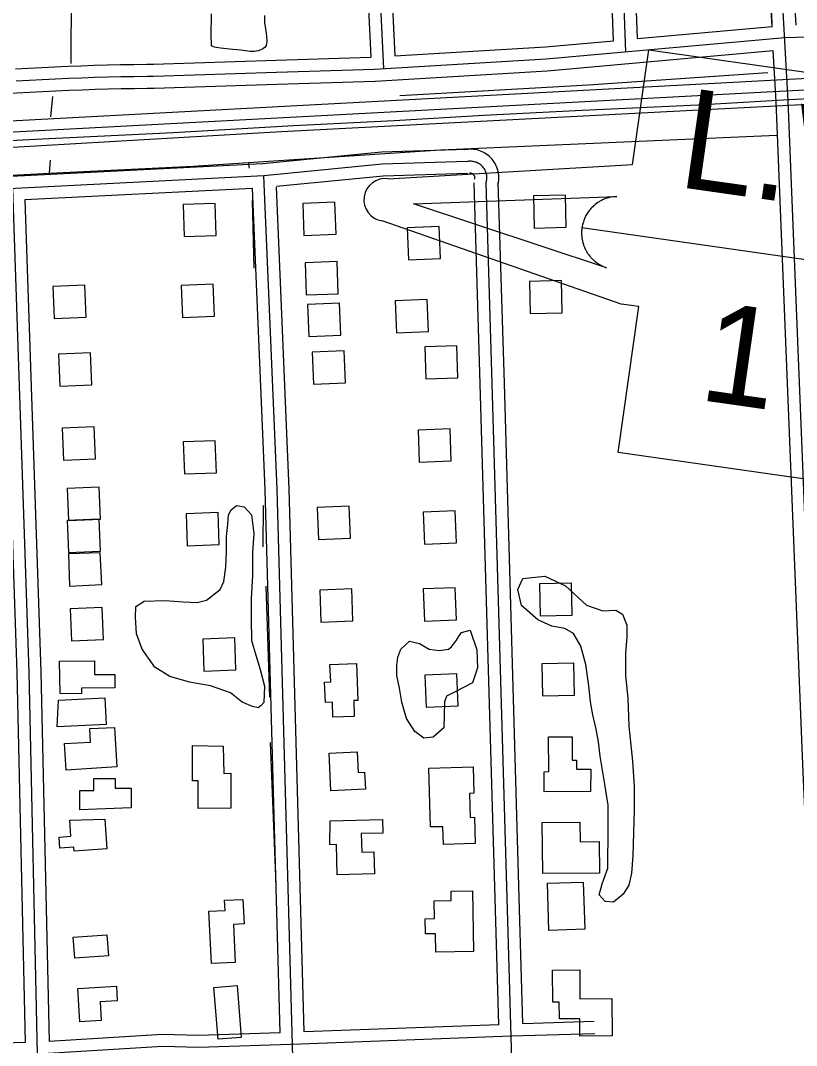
# Model space of a CAD drawing. Extents: x 3508733 to 3546731, y 546897 to 572481.
# Drawn here: x 3525636 to 3526605, y 567338 to 568617 of the extents above; entities that cross this region are included whole.
import ezdxf

# ---------------------------------------------------------------- set-up
doc = ezdxf.new("R2010")
doc.units = 0
for name, color, linetype in [('V-BLDG-OTLN', 7, 'Continuous'), ('V-RAIL-TRAK', 7, 'Continuous'), ('V-ROAD-CNTR', 7, 'Continuous'), ('V-SITE-VEGE', 7, 'Continuous'), ('V-TOPO-SHOR', 7, 'Continuous'), ('V-TOPO-WATR-IDEN', 7, 'Continuous')]:
    doc.layers.add(name, color=color, linetype=linetype)

msp = doc.modelspace()

# ---------------------------------------------------------------- linework, layer by layer
at = {"layer": 'V-BLDG-OTLN'}
for points in [[(3526276.5, 568398.4), (3526277.4, 568358.4), (3526317.4, 568359.3), (3526316.5, 568399.3)], [(3525839.3, 568387.7), (3525840.8, 568347.8), (3525880.7, 568349.2), (3525879.3, 568389.2)], [(3525988.6, 568389), (3525990.1, 568349), (3526030.1, 568350.6), (3526028.6, 568390.5)], [(3526118.8, 568358.7), (3526120.4, 568318.7), (3526160.3, 568320.2), (3526158.8, 568360.2)], [(3525991.4, 568314.9), (3525993, 568274.9), (3526032.9, 568276.4), (3526031.4, 568316.4)], [(3526271.4, 568291.8), (3526272.2, 568251.8), (3526312.2, 568252.7), (3526311.4, 568292.7)], [(3525678.2, 568245.5), (3525718.2, 568247.2), (3525716.5, 568287.2), (3525676.6, 568285.5)], [(3525836.9, 568286.8), (3525838.4, 568246.8), (3525878.3, 568248.2), (3525876.9, 568288.2)], [(3525994.5, 568263.1), (3525996.1, 568223.1), (3526036, 568224.6), (3526034.5, 568264.6)], [(3526104, 568267.5), (3526105.5, 568227.5), (3526145.5, 568229.1), (3526144, 568269)], [(3525685.5, 568160.9), (3525725.5, 568162.6), (3525723.8, 568202.5), (3525683.8, 568200.8)], [(3526000.3, 568203.6), (3526001.8, 568163.6), (3526041.8, 568165.2), (3526040.3, 568205.1)], [(3526140.7, 568210), (3526142.3, 568170), (3526182.2, 568171.5), (3526180.7, 568211.5)], [(3525689.9, 568068.6), (3525729.8, 568070.3), (3525728.2, 568110.3), (3525688.2, 568108.6)], [(3526132.4, 568106.2), (3526133.9, 568066.2), (3526173.9, 568067.7), (3526172.3, 568107.7)], [(3525839.5, 568091.4), (3525840.9, 568051.4), (3525880.9, 568052.9), (3525879.4, 568092.8)], [(3525696.1, 567993.4), (3525736.1, 567995.1), (3525734.4, 568035), (3525694.5, 568033.4)], [(3526006.6, 568009.6), (3526008.2, 567969.6), (3526048.1, 567971.1), (3526046.6, 568011.1)], [(3525696.4, 567953.4), (3525736.4, 567955.1), (3525734.7, 567995), (3525694.7, 567993.4)], [(3525843, 568001.8), (3525844.4, 567961.8), (3525884.4, 567963.3), (3525883, 568003.2)], [(3526138.7, 568003.8), (3526140.3, 567963.8), (3526180.2, 567965.4), (3526178.7, 568005.3)], [(3525697.7, 567911.5), (3525737.7, 567913.2), (3525736, 567953.1), (3525696.1, 567951.5)], [(3526009.7, 567906.4), (3526011.2, 567866.4), (3526051.1, 567867.9), (3526049.6, 567907.9)], [(3526138.9, 567907.8), (3526140.4, 567867.8), (3526180.4, 567869.3), (3526178.8, 567909.3)], [(3526284, 567914.4), (3526284.9, 567874.4), (3526324.9, 567875.3), (3526324, 567915.2)], [(3525699.9, 567842.9), (3525739.9, 567844.6), (3525738.2, 567884.6), (3525698.2, 567882.9)], [(3525863.7, 567845.3), (3525865.1, 567805.3), (3525905.1, 567806.8), (3525903.7, 567846.7)], [(3525685.7, 567777.2), (3525685.2, 567817.5), (3525728.6, 567818), (3525728.8, 567801), (3525754.1, 567801.2), (3525754.3, 567784.5), (3525712.7, 567784), (3525712.7, 567776.9)], [(3526286.9, 567814.3), (3526287.8, 567774.3), (3526327.8, 567775.2), (3526326.9, 567815.2)], [(3526055.5, 567814.8), (3526057.2, 567768.8), (3526052.1, 567768.6), (3526052.9, 567748.7), (3526026.2, 567747.7), (3526025.5, 567766.4), (3526016.9, 567766.1), (3526015.9, 567791.6), (3526023.4, 567791.9), (3526022.5, 567813.6)], [(3526141, 567800.4), (3526142.6, 567760.4), (3526182.5, 567762), (3526181, 567801.9)], [(3525683.7, 567769), (3525741.7, 567771.9), (3525743.4, 567738.7), (3525682.2, 567735.6)], [(3525753.5, 567734.7), (3525756.5, 567685.6), (3525693.4, 567681.8), (3525691.4, 567714.8), (3525723.9, 567716.7), (3525722.9, 567733.6)], [(3526347.7, 567654.9), (3526289.8, 567654.5), (3526289.6, 567679.7), (3526295.5, 567679.8), (3526295.2, 567723.2), (3526324.7, 567723.4), (3526324.9, 567694.1), (3526330.2, 567694.1), (3526330.3, 567682.7), (3526348.1, 567682.8)], [(3525889.4, 567711.5), (3525889.9, 567677.5), (3525898.8, 567677.8), (3525899, 567634.1), (3525858.2, 567633.8), (3525858, 567668.2), (3525850.9, 567668.3), (3525850.9, 567712.3)], [(3526021.7, 567702.8), (3526056.3, 567704.6), (3526057.6, 567678.8), (3526065.7, 567679.2), (3526066.8, 567658), (3526023.4, 567655.8)], [(3526147.9, 567611), (3526145.7, 567684.1), (3526201, 567685.8), (3526202, 567652.9), (3526196.5, 567652.7), (3526197.4, 567622.7), (3526202.8, 567622.9), (3526203.8, 567590), (3526164.2, 567588.8), (3526163.5, 567610.9)], [(3525710.3, 567632.3), (3525710.4, 567656.2), (3525728, 567656.1), (3525728.1, 567671.2), (3525754.5, 567671.1), (3525754.5, 567659.2), (3525774.6, 567659.1), (3525774.5, 567634.5)], [(3525741.7, 567620.5), (3525744, 567583.3), (3525703.3, 567580.7), (3525703, 567585.5), (3525685.4, 567584.3), (3525684.5, 567598.2), (3525699.4, 567599.1), (3525698.1, 567619.2)], [(3526022.6, 567618.4), (3526088.1, 567620.1), (3526088.5, 567603.1), (3526061.6, 567602.4), (3526062.1, 567579.3), (3526077.2, 567579.6), (3526077.9, 567552.1), (3526031.7, 567550.9), (3526030.8, 567588.8), (3526022.5, 567588.6)], [(3526288.1, 567552.5), (3526287.1, 567616.1), (3526334.3, 567616.9), (3526334.7, 567592), (3526358.2, 567592.4), (3526358.8, 567553)], [(3526293.9, 567540.6), (3526338.6, 567541.9), (3526340.4, 567483), (3526295.7, 567481.6)], [(3526200.4, 567531), (3526201.7, 567455.2), (3526154.4, 567454.4), (3526154, 567477.5), (3526141.8, 567477.3), (3526141.5, 567496.2), (3526153, 567496.4), (3526152.6, 567518.7), (3526173.9, 567519.1), (3526173.7, 567530.6)], [(3525874.5, 567440.1), (3525871.5, 567505.7), (3525891.6, 567506.6), (3525891, 567519.2), (3525913.9, 567520.2), (3525915.3, 567489.7), (3525902.1, 567489.1), (3525904.2, 567441.4)], [(3525702.2, 567473.1), (3525744.2, 567476), (3525746, 567449.8), (3525704, 567446.9)], [(3526374.7, 567350), (3526334.4, 567349.7), (3526334.2, 567371.4), (3526308.8, 567371.2), (3526308.6, 567392.1), (3526300.7, 567392), (3526300.3, 567432), (3526334.1, 567432.2), (3526334.4, 567396.2), (3526374.3, 567396.5)], [(3525710.6, 567367.5), (3525707.9, 567409), (3525756, 567412.1), (3525757.1, 567393.7), (3525735.6, 567392.4), (3525737.1, 567369.2)], [(3525883, 567345.8), (3525877.7, 567410.4), (3525906.6, 567412.7), (3525911.8, 567348.1)]]:
    msp.add_lwpolyline(points, close=True, dxfattribs=at)
at = {"layer": 'V-RAIL-TRAK'}
msp.add_lwpolyline([(3524938.2, 568432.3), (3525056, 568438.4), (3525184.8, 568444.9), (3525309.6, 568450), (3525443.1, 568457.1), (3525498.6, 568460.8), (3525527.5, 568462.7), (3525663.6, 568469.7), (3525827.4, 568477.6), (3525977, 568486.2), (3526102.7, 568492.6), (3526214.5, 568499.4), (3526337.1, 568505.5), (3526481.3, 568512.2), (3526595.6, 568518.7), (3526628.2, 568520.6), (3526822.2, 568530.2), (3527016.6, 568540.8), (3527139.8, 568547.4), (3527180.4, 568549.6), (3527314.3, 568557.8), (3527408.8, 568562.5)], dxfattribs=at)
at = {"layer": 'V-ROAD-CNTR'}
for points in [[(3526004.6, 570572), (3526009.4, 570400.2), (3526023.7, 569984.7), (3526032.2, 569739.6), (3526043.8, 569339.4), (3526061.5, 568823.8), (3526073.6, 568571.6)], [(3526019.6, 570572.4), (3526024.4, 570400.7), (3526038.7, 569985.2), (3526047.2, 569740.1), (3526058.8, 569339.9), (3526076.5, 568824.4), (3526089.3, 568557.4)], [(3526391.7, 568578.4), (3526379.7, 568905.7), (3526344.6, 569873.6), (3526316.7, 570574.4)], [(3526604, 568611.6), (3526601.4, 568659.4), (3526573.1, 569255.4), (3526550.4, 569775.1), (3526512.9, 570575.8)], [(3526676.5, 566599.1), (3526669.5, 566768.5), (3526656.3, 567062.3), (3526627.9, 567679.2), (3526594.2, 568517), (3526586.4, 568658.6), (3526558.1, 569254.7), (3526535.5, 569774.4), (3526498.4, 570565.7)], [(3526406.1, 568594.8), (3526394.7, 568906.3), (3526364.7, 569734.8)], [(3526574.1, 568609.8), (3526571.4, 568657.8), (3526543.2, 569254), (3526522, 569739.8)], [(3526062.6, 569725.6), (3526073.8, 569340.3), (3526091.5, 568825), (3526103.5, 568573.3)], [(3526376.2, 568592.1), (3526364.8, 568905.2), (3526334.7, 569733.9)], [(3533541.7, 568893.8), (3532987.5, 568867.6), (3532205, 568827.4), (3531013.4, 568763.7), (3530019.9, 568712.5), (3529348.3, 568675.3), (3528491.3, 568630.8), (3527524, 568577.8), (3526567.5, 568528), (3525471, 568469.9), (3524754.5, 568430.6), (3524144.7, 568396.6), (3523696.6, 568373.6)], [(3529659.4, 568707.9), (3529141, 568683.1), (3528588.6, 568651.6), (3528099.7, 568623.8), (3526751, 568552), (3525561.1, 568488.5), (3525167, 568468.1)], [(3525802.5, 568548), (3525955.8, 568552.9), (3526078.2, 568556.7), (3526292.4, 568569.5), (3526590, 568596.1), (3526983.7, 568607.8), (3527362.7, 568625.3), (3527808.8, 568642.5), (3527919.3, 568652.8), (3528045.1, 568673.5)], [(3526406.1, 568594.8), (3526574.1, 568609.8)], [(3526103.5, 568573.3), (3526291.3, 568584.5), (3526376.2, 568592.1)], [(3525802, 568563), (3525955.4, 568567.9), (3526073.6, 568571.6)], [(3525803, 568533), (3525956.3, 568537.9), (3526078.9, 568541.7), (3526293.5, 568554.6), (3526575.7, 568579.8)], [(3526660.9, 566613.7), (3526654.5, 566767.9), (3526641.3, 567061.6), (3526612.9, 567678.6), (3526579.3, 568516.3), (3526575.7, 568579.8)], [(3525630.1, 568557), (3525646.5, 568558), (3525662.9, 568558.9), (3525679.3, 568559.7), (3525695.7, 568560.4), (3525712.1, 568561), (3525728.5, 568561.6), (3525744.9, 568562), (3525761.3, 568562.4), (3525777.7, 568562.7), (3525794.1, 568563), (3525802.3, 568563)], [(3527261.3, 568548.2), (3526964.1, 568530.6), (3525962.1, 568478.6), (3525490.3, 568450.9), (3524954.9, 568426.5)], [(3525631, 568542.1), (3525647.3, 568543), (3525663.6, 568543.9), (3525680, 568544.7), (3525696.3, 568545.4), (3525712.6, 568546), (3525728.9, 568546.6), (3525745.3, 568547), (3525761.6, 568547.4), (3525778, 568547.7), (3525794.3, 568548), (3525802.5, 568548)], [(3525507.7, 568517.3), (3525534.5, 568519.8), (3525550.8, 568521.2), (3525567, 568522.5), (3525583.2, 568523.8), (3525599.4, 568525), (3525615.7, 568526.1), (3525631.9, 568527.1), (3525648.1, 568528), (3525664.4, 568528.9), (3525680.6, 568529.7), (3525696.9, 568530.4), (3525713.2, 568531), (3525729.4, 568531.6), (3525745.7, 568532), (3525761.9, 568532.4), (3525778.2, 568532.7), (3525794.5, 568533), (3525802.6, 568533)], [(3526193.1, 568456.3), (3526086.8, 568452.9), (3525938.9, 568438.6), (3525517, 568417.1)], [(3526232, 568411.5), (3526232.4, 568413.2), (3526232.8, 568415.4), (3526233.1, 568417.6), (3526233.3, 568419.8), (3526233.3, 568422), (3526233.2, 568424.3), (3526232.9, 568426.5), (3526232.5, 568428.6), (3526232, 568430.8), (3526231.3, 568432.9), (3526230.5, 568435), (3526229.6, 568437), (3526228.6, 568439), (3526227.4, 568440.8), (3526226.1, 568442.6), (3526224.7, 568444.4), (3526223.2, 568446), (3526221.6, 568447.6), (3526219.9, 568449), (3526218.2, 568450.3), (3526216.3, 568451.5), (3526214.4, 568452.6), (3526212.4, 568453.6), (3526210.3, 568454.5), (3526208.2, 568455.2), (3526206.1, 568455.8), (3526203.9, 568456.2), (3526201.7, 568456.5), (3526199.5, 568456.7), (3526197.3, 568456.7), (3526195.1, 568456.6), (3526192.9, 568456.4), (3526190.9, 568456.1), (3526190.5, 568456)], [(3526193.6, 568441.3), (3526087.7, 568438), (3525940, 568423.6), (3525450, 568398.7), (3525397.2, 568395.3)], [(3526217.5, 568415.4), (3526217.8, 568416.6), (3526218, 568417.9), (3526218.2, 568419.1), (3526218.3, 568420.4), (3526218.3, 568421.7), (3526218.2, 568423), (3526218.1, 568424.2), (3526217.8, 568425.5), (3526217.5, 568426.8), (3526217.2, 568428), (3526216.7, 568429.2), (3526216.2, 568430.3), (3526215.6, 568431.5), (3526214.9, 568432.6), (3526214.1, 568433.6), (3526213.3, 568434.6), (3526212.5, 568435.5), (3526211.6, 568436.4), (3526210.6, 568437.3), (3526209.6, 568438), (3526208.5, 568438.7), (3526207.4, 568439.4), (3526206.2, 568439.9), (3526205, 568440.4), (3526203.8, 568440.8), (3526202.6, 568441.2), (3526201.3, 568441.4), (3526200.1, 568441.6), (3526198.8, 568441.7), (3526197.5, 568441.7), (3526196.2, 568441.7), (3526195, 568441.5), (3526193.7, 568441.3), (3526193.6, 568441.3)], [(3525989, 566937.2), (3525977.3, 567278), (3525956.7, 568032.5), (3525940, 568423.6)], [(3526194.1, 568426.3), (3526088.7, 568423), (3525955.6, 568410.1)], [(3526202.9, 568419.2), (3526203.2, 568420), (3526203.2, 568420.3), (3526203.3, 568420.7), (3526203.3, 568421), (3526203.3, 568421.4), (3526203.3, 568421.7), (3526203.2, 568422), (3526203.2, 568422.4), (3526203.1, 568422.7), (3526203, 568423), (3526202.9, 568423.4), (3526202.7, 568423.7), (3526202.6, 568424), (3526202.4, 568424.3), (3526202.2, 568424.5), (3526202, 568424.8), (3526201.7, 568425.1), (3526201.5, 568425.3), (3526201.2, 568425.5), (3526201, 568425.7), (3526200.7, 568425.9), (3526200.4, 568426.1), (3526200.1, 568426.2), (3526199.7, 568426.4), (3526199.4, 568426.5), (3526199.1, 568426.6), (3526198.7, 568426.6), (3526198.4, 568426.7), (3526198.1, 568426.7), (3526197.7, 568426.7), (3526197.4, 568426.7), (3526197, 568426.7), (3526196.5, 568426.6), (3526196.7, 568426.6)], [(3525626.5, 568407.7), (3525646.7, 567804), (3525657.4, 567327.1), (3525520, 567322.8)], [(3525925.7, 568407.9), (3525642, 568393.4)], [(3525960.3, 567353.7), (3525941.7, 568032), (3525925.7, 568407.9)], [(3525990.2, 567354.8), (3525971.7, 568033), (3525955.6, 568409.4)], [(3526233.1, 567363.8), (3526228.9, 567507.4), (3526210.1, 568163.7), (3526202.5, 568414.9)], [(3526262.5, 566871.9), (3526243.9, 567507.8), (3526225.1, 568164.2), (3526217.5, 568415.4)], [(3526263.1, 567364.8), (3526258.9, 567508.3), (3526240.1, 568164.6), (3526232.4, 568415.8)], [(3525612, 568391.9), (3525631.7, 567803.6), (3525642.1, 567341.6), (3525533.1, 567338.2)], [(3525642, 568393.4), (3525661.7, 567804.4), (3525672, 567343)], [(3526352.3, 567367.7), (3526263.1, 567364.8)], [(3526233.1, 567363.8), (3525990.2, 567354.8)], [(3526352.8, 567352.7), (3526248.4, 567349.4), (3525986.3, 567339.7), (3525858.4, 567335.6), (3525814, 567336.7), (3525657.4, 567327.1)], [(3525960.3, 567353.8), (3525858.3, 567350.6), (3525813.7, 567351.7), (3525672, 567343)]]:
    msp.add_lwpolyline(points, dxfattribs=at)
at = {"layer": 'V-SITE-VEGE'}
for p, q in [((3525874.3, 568598.4), (3525874.6, 568625.6)), ((3525940.9, 568623.8), (3525940.8, 568614.7)), ((3525940.8, 568614.7), (3525941.5, 568609.8)), ((3525941.5, 568609.8), (3525942.9, 568601.8)), ((3525874.6, 568588.5), (3525874.3, 568598.4)), ((3525942.9, 568601.8), (3525943.2, 568597.7)), ((3525943.2, 568597.7), (3525943.9, 568591.2)), ((3525874.6, 568585.9), (3525874.6, 568588.5)), ((3525878.3, 568584.3), (3525874.6, 568585.9)), ((3525885.9, 568583.1), (3525878.3, 568584.3)), ((3525901.4, 568581.1), (3525885.9, 568583.1)), ((3525941.6, 568584.1), (3525938.9, 568582.2)), ((3525942.8, 568586.3), (3525941.6, 568584.1)), ((3525943.9, 568591.2), (3525942.8, 568586.3)), ((3525911.2, 568580.2), (3525901.4, 568581.1)), ((3525923, 568578.9), (3525911.2, 568580.2)), ((3525928.3, 568578.9), (3525923, 568578.9)), ((3525933.2, 568579.6), (3525928.3, 568578.9)), ((3525938.9, 568582.2), (3525933.2, 568579.6))]:
    msp.add_line(p, q, dxfattribs=at)
for points in [[(3525940.8, 567786.4), (3525939.9, 567766.3), (3525936.8, 567762.5), (3525932.9, 567759.4), (3525926, 567761), (3525912.9, 567766.4), (3525898.3, 567778.1), (3525873.6, 567786.7), (3525847.3, 567791.4), (3525822.7, 567798.4), (3525804.2, 567810.1), (3525788, 567832.6), (3525781.2, 567851.9), (3525779.7, 567872.8), (3525780.5, 567885.9), (3525790.6, 567892.8), (3525816.8, 567893.5), (3525839.2, 567891.8), (3525857, 567891), (3525868.6, 567894), (3525885.6, 567907.1), (3525890.3, 567917.1), (3525892.7, 567934.9), (3525893.5, 567954.2), (3525893.6, 567973.5), (3525895.2, 567988.1), (3525896, 568000.5), (3525899.2, 568006.7), (3525906.1, 568012), (3525915.4, 568010.5), (3525924.6, 568000.4), (3525927.6, 567977.2), (3525926, 567953.3), (3525925.9, 567924.7), (3525924.2, 567896.1), (3525924.1, 567870.6), (3525924.8, 567843.6), (3525930.1, 567825.1), (3525935.4, 567807.3)], [(3526398.6, 567552.9), (3526395.5, 567538.2), (3526388.5, 567526.7), (3526376.1, 567516.7), (3526366, 567517.5), (3526358.3, 567526), (3526362.2, 567539.9), (3526369.3, 567559.2), (3526369.5, 567610.2), (3526369.6, 567638), (3526365.1, 567666.6), (3526359.8, 567699), (3526357.5, 567716.8), (3526354.5, 567733), (3526350.7, 567750.8), (3526347.7, 567767), (3526345.5, 567787.1), (3526341.7, 567813.4), (3526335.6, 567836.6), (3526326.4, 567852.1), (3526315.6, 567858.3), (3526299.4, 567861.4), (3526281.7, 567869.2), (3526261.7, 567887.1), (3526257.1, 567907.2), (3526263.3, 567921), (3526290.4, 567924), (3526316.6, 567911.6), (3526342.8, 567887.5), (3526362.8, 567880.5), (3526379, 567881.2), (3526387.5, 567876.5), (3526392.9, 567862.6), (3526392.8, 567847.9), (3526391.2, 567827.1), (3526391.1, 567799.3), (3526394.1, 567771.5), (3526395.5, 567736.7), (3526399.9, 567692.7), (3526402.1, 567661.8), (3526402, 567631.7), (3526400.2, 567575.3)], [(3526197.4, 567856.4), (3526205.8, 567831.7), (3526206.5, 567809.3), (3526200.3, 567790.8), (3526178.6, 567779.3), (3526167.8, 567773.9), (3526165.4, 567767), (3526164.5, 567734.5), (3526151.4, 567723), (3526139.8, 567721.5), (3526128.2, 567730.1), (3526118.2, 567746.3), (3526112.1, 567766.4), (3526109.1, 567784.2), (3526106.1, 567799.6), (3526106.1, 567812.8), (3526107, 567822.8), (3526110.9, 567832.8), (3526121.7, 567842.8), (3526134.1, 567839.7), (3526146.4, 567832.7), (3526158.7, 567831.1), (3526170.3, 567832.6), (3526174.2, 567835.7), (3526180.4, 567844.1), (3526182.7, 567848), (3526186.6, 567853.4)]]:
    msp.add_lwpolyline(points, close=True, dxfattribs=at)
at = {"layer": 'V-TOPO-SHOR'}
for p, q in [((3525674.2, 568497.2), (3525676.9, 568522.4)), ((3525672.7, 568426.7), (3525674, 568443)), ((3525922.2, 568433.1), (3525921, 568440.3)), ((3525928, 568308.3), (3525925.8, 568392.7)), ((3525939.2, 567960.6), (3525939.4, 568012.2)), ((3525947.3, 567772.8), (3525942.8, 567911.4)), ((3525955.2, 567538.5), (3525948.3, 567716.1))]:
    msp.add_line(p, q, dxfattribs=at)
for points in [[(3525699.7, 568563.9), (3525701.1, 568920.4), (3525687.8, 569375.2), (3525673.4, 569888), (3525663.4, 570225.7), (3525660.9, 570298.2), (3525652.1, 570552), (3525651.6, 570566.7)], [(3526574.3, 568609.3), (3526567.8, 568897.8), (3526545.3, 569244.4), (3526524.2, 569647.6), (3526520.7, 569732)], [(3526109.6, 568524), (3526344.7, 568537.1), (3526569, 568552.6)], [(3525530.4, 568419.4), (3525672.7, 568426.7), (3525851.7, 568435.8), (3525921, 568440.3), (3526160.4, 568456), (3526580, 568474.5)]]:
    msp.add_lwpolyline(points, dxfattribs=at)
at = {"layer": 'V-TOPO-WATR-IDEN'}
msp.add_line((3527080.6, 568252.6), (3526336.9, 568358.6), dxfattribs=at)
for points in [[(3526095.1, 568419.8), (3526400.1, 568437.7), (3526420.5, 568581), (3527052.6, 568490.9), (3527032.2, 568347.6), (3527329.8, 568243.8)], [(3527322.3, 568191.4), (3526997.1, 568176.4), (3526977.6, 568179.2), (3526951.6, 567997), (3526381.9, 568078.2), (3526407.8, 568260.4), (3526386, 568263.5), (3526087.7, 568367.4)]]:
    msp.add_lwpolyline(points, dxfattribs=at)
msp.add_lwpolyline([(3526367.7, 568308.8), (3526126.6, 568388.6), (3526380.4, 568397.9), (3526375.8, 568397.5), (3526371.5, 568396.6), (3526369.8, 568396.2), (3526368.3, 568395.7), (3526366.5, 568395.1), (3526364.8, 568394.5), (3526363.3, 568393.8), (3526361.4, 568392.9), (3526359.3, 568391.8), (3526358.2, 568391.1), (3526356.8, 568390.2), (3526355, 568388.9), (3526353.6, 568387.9), (3526352.2, 568386.7), (3526351.3, 568385.9), (3526350.3, 568385), (3526349.1, 568383.8), (3526348.1, 568382.7), (3526347.1, 568381.6), (3526346.4, 568380.6), (3526345.2, 568379.1), (3526344.2, 568377.7), (3526343.5, 568376.5), (3526342.6, 568375.1), (3526341.9, 568373.9), (3526341.3, 568372.7), (3526340.9, 568371.9), (3526340.3, 568370.5), (3526339.7, 568369.1), (3526339.2, 568367.7), (3526338.7, 568366.3), (3526338.3, 568365), (3526337.9, 568363.5), (3526337.6, 568362.3), (3526337.2, 568360.6), (3526336.9, 568358.6), (3526336.8, 568358), (3526336.7, 568357.1), (3526336.6, 568356), (3526336.5, 568354.9), (3526336.5, 568353.9), (3526336.4, 568352.9), (3526336.4, 568351.7), (3526336.5, 568350.8), (3526336.5, 568349.6), (3526336.6, 568348.5), (3526336.7, 568347.7), (3526336.9, 568345.7), (3526337.1, 568344.6), (3526337.2, 568343.9), (3526337.4, 568342.7), (3526337.7, 568341.6), (3526337.9, 568340.5), (3526338.3, 568339.2), (3526338.7, 568338), (3526339, 568337.1), (3526339.3, 568336.3), (3526339.7, 568335.2), (3526340.1, 568334.3), (3526340.5, 568333.2), (3526341.1, 568332.1), (3526341.6, 568331), (3526342.4, 568329.6), (3526342.9, 568328.7), (3526343.6, 568327.6), (3526344.2, 568326.6), (3526344.8, 568325.8), (3526345.4, 568325), (3526346.3, 568323.7), (3526346.4, 568323.7), (3526347, 568323), (3526347.4, 568322.4), (3526348.1, 568321.6), (3526349, 568320.7), (3526349.7, 568320), (3526350.3, 568319.3), (3526351.2, 568318.5), (3526352, 568317.7), (3526352.6, 568317.2), (3526353.5, 568316.5), (3526354.6, 568315.6), (3526355.3, 568315.1), (3526355.9, 568314.7), (3526356.4, 568314.4), (3526357, 568314), (3526357.8, 568313.4), (3526358.7, 568312.9), (3526359.5, 568312.4), (3526360.3, 568312), (3526361.4, 568311.4), (3526362.1, 568311), (3526363.2, 568310.5), (3526364.5, 568310), (3526365.4, 568309.6), (3526366.1, 568309.3), (3526366.8, 568309.1), (3526367.3, 568308.9)], close=True, dxfattribs=at)
msp.add_arc((3526091.4, 568393.6), 26.5, 81.8872, 261.8872, dxfattribs=at)

# ---------------------------------------------------------------- texts
for s, rotation, p in [('L.W.R.P.', 351.8871, (3526454.5, 568410)), ('1', 351.8873, (3526481, 568144.1))]:
    msp.add_text(s, height=124.5, rotation=rotation, dxfattribs=at).set_placement(p)

doc.saveas('drawing.dxf')
